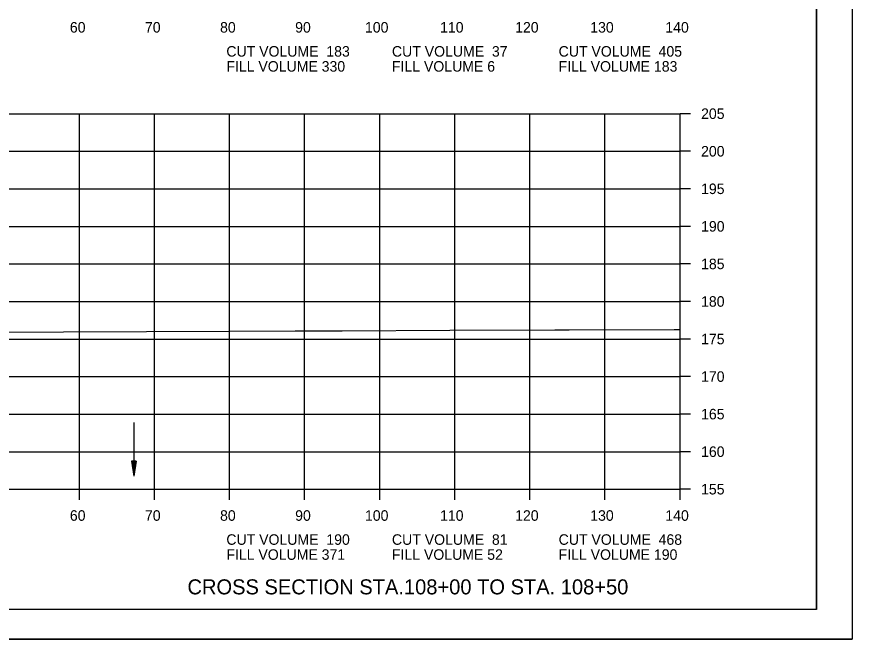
# Model space of a CAD drawing. Extents: x 1372132 to 1372465, y 380083 to 381790.
# Drawn here: x 1372353.7 to 1372464.9, y 381150.2 to 381233.1 of the extents above; entities that cross this region are included whole.
import ezdxf

# ---------------------------------------------------------------- set-up
doc = ezdxf.new("R2010")
doc.units = 0
for name, color, linetype in [('R_Axis', 7, 'Continuous'), ('R_Axis Annot', 7, 'Continuous'), ('R_Border', 7, 'Continuous'), ('R_Dimension', 7, 'Continuous'), ('R_Draft', 7, 'Continuous'), ('R_Exist Surface', 7, 'Continuous'), ('R_Grid', 7, 'Continuous'), ('R_No Plot', 7, 'Continuous')]:
    doc.layers.add(name, color=color, linetype=linetype)

msp = doc.modelspace()

# ---------------------------------------------------------------- linework, layer by layer
at = {"layer": 'R_Axis'}
for p, q in [((1372442.01, 381170.16), (1372442.01, 381220.16)), ((1372443.41, 381220.16), (1372442.01, 381220.16)), ((1372443.41, 381215.16), (1372442.01, 381215.16)), ((1372443.41, 381210.16), (1372442.01, 381210.16)), ((1372443.41, 381205.16), (1372442.01, 381205.16)), ((1372443.41, 381200.16), (1372442.01, 381200.16)), ((1372443.41, 381195.16), (1372442.01, 381195.16)), ((1372443.41, 381190.16), (1372442.01, 381190.16)), ((1372443.41, 381185.16), (1372442.01, 381185.16)), ((1372443.41, 381180.16), (1372442.01, 381180.16)), ((1372443.41, 381175.16), (1372442.01, 381175.16)), ((1372162.01, 381170.16), (1372442.01, 381170.16)), ((1372362.01, 381168.76), (1372362.01, 381170.16)), ((1372372.01, 381168.76), (1372372.01, 381170.16)), ((1372382.01, 381168.76), (1372382.01, 381170.16)), ((1372392.01, 381168.76), (1372392.01, 381170.16)), ((1372402.01, 381168.76), (1372402.01, 381170.16)), ((1372412.01, 381168.76), (1372412.01, 381170.16)), ((1372422.01, 381168.76), (1372422.01, 381170.16)), ((1372432.01, 381168.76), (1372432.01, 381170.16)), ((1372442.01, 381168.76), (1372442.01, 381170.16)), ((1372443.41, 381170.16), (1372442.01, 381170.16))]:
    msp.add_line(p, q, dxfattribs=at)
at = {"layer": 'R_Border'}
for q in [(1372460.19, 381359.62), (1372144.01, 381154.16)]:
    msp.add_line((1372460.19, 381154.16), q, dxfattribs=at)
at = {"layer": 'R_Dimension'}
for p, q in [((1372368.96, 381173.89), (1372369.26, 381171.89)), ((1372369.56, 381173.89), (1372368.96, 381173.89)), ((1372368.96, 381173.89), (1372369.26, 381171.89)), ((1372369.56, 381173.89), (1372368.96, 381173.89)), ((1372369.01, 381173.89), (1372369.26, 381172.23)), ((1372369.01, 381173.89), (1372369.26, 381172.23)), ((1372369.06, 381173.89), (1372369.26, 381172.57)), ((1372369.06, 381173.89), (1372369.26, 381172.57)), ((1372369.11, 381173.89), (1372369.26, 381172.9)), ((1372369.11, 381173.89), (1372369.26, 381172.9)), ((1372369.16, 381173.89), (1372369.26, 381173.24)), ((1372369.16, 381173.89), (1372369.26, 381173.24)), ((1372369.21, 381173.89), (1372369.26, 381173.58)), ((1372369.21, 381173.89), (1372369.26, 381173.58)), ((1372369.56, 381173.89), (1372369.26, 381171.89)), ((1372369.36, 381173.89), (1372369.26, 381173.24)), ((1372369.46, 381173.89), (1372369.26, 381172.57)), ((1372369.51, 381173.89), (1372369.26, 381172.23)), ((1372369.41, 381173.89), (1372369.26, 381172.9)), ((1372369.31, 381173.89), (1372369.26, 381173.58)), ((1372369.56, 381173.89), (1372369.26, 381171.89)), ((1372369.36, 381173.89), (1372369.26, 381173.24)), ((1372369.46, 381173.89), (1372369.26, 381172.57)), ((1372369.51, 381173.89), (1372369.26, 381172.23)), ((1372369.41, 381173.89), (1372369.26, 381172.9)), ((1372369.31, 381173.89), (1372369.26, 381173.58))]:
    msp.add_line(p, q, dxfattribs=at)
at = {"layer": 'R_Draft'}
msp.add_line((1372369.26, 381179.03), (1372369.26, 381171.89), dxfattribs=at)
at = {"layer": 'R_Exist Surface'}
msp.add_lwpolyline([(1372348.79, 381191.05), (1372382, 381191.2), (1372390.77, 381191.23), (1372395.4, 381191.25), (1372396.19, 381191.26), (1372397.03, 381191.26), (1372411.33, 381191.32), (1372425.35, 381191.38), (1372427.22, 381191.37), (1372441.23, 381191.43), (1372442.01, 381191.43)], dxfattribs=at)
at = {"layer": 'R_Grid'}
for p, q in [((1372162.01, 381220.16), (1372442.01, 381220.16)), ((1372362.01, 381170.16), (1372362.01, 381220.16)), ((1372372.01, 381170.16), (1372372.01, 381220.16)), ((1372382.01, 381170.16), (1372382.01, 381220.16)), ((1372392.01, 381170.16), (1372392.01, 381220.16)), ((1372402.01, 381170.16), (1372402.01, 381220.16)), ((1372412.01, 381170.16), (1372412.01, 381220.16)), ((1372422.01, 381170.16), (1372422.01, 381220.16)), ((1372432.01, 381170.16), (1372432.01, 381220.16)), ((1372442.01, 381170.16), (1372442.01, 381220.16)), ((1372162.01, 381215.16), (1372442.01, 381215.16)), ((1372162.01, 381210.16), (1372442.01, 381210.16)), ((1372162.01, 381205.16), (1372442.01, 381205.16)), ((1372162.01, 381200.16), (1372442.01, 381200.16)), ((1372162.01, 381195.16), (1372442.01, 381195.16)), ((1372162.01, 381190.16), (1372442.01, 381190.16)), ((1372162.01, 381185.16), (1372442.01, 381185.16)), ((1372162.01, 381180.16), (1372442.01, 381180.16)), ((1372162.01, 381175.16), (1372442.01, 381175.16)), ((1372162.01, 381170.16), (1372442.01, 381170.16))]:
    msp.add_line(p, q, dxfattribs=at)
at = {"layer": 'R_No Plot'}
msp.add_line((1372131.61, 381150.18), (1372464.95, 381150.18), dxfattribs=at)
for points in [[(1372131.61, 381363.52), (1372464.95, 381363.52), (1372464.95, 381150.18), (1372131.61, 381150.18)], [(1372377.93, 381359.62), (1372377.93, 381349.74), (1372413.67, 381349.74), (1372413.67, 381346.82), (1372436.87, 381346.82), (1372436.87, 381322.49), (1372460.19, 381322.49), (1372460.19, 381154.16), (1372144.01, 381154.16), (1372144.01, 381359.62)]]:
    msp.add_lwpolyline(points, close=True, dxfattribs=at)

# ---------------------------------------------------------------- texts
at = {"layer": 'R_Axis Annot'}
for s, p in [('60', (1372360.75, 381230.96)), ('70', (1372370.75, 381230.96)), ('80', (1372380.75, 381230.96)), ('90', (1372390.75, 381230.96)), ('100', (1372400.05, 381230.96)), ('110', (1372410.05, 381230.96)), ('120', (1372420.05, 381230.96)), ('130', (1372430.05, 381230.96)), ('140', (1372440.05, 381230.96)), ('CUT VOLUME  183', (1372381.59, 381227.76)), ('CUT VOLUME  37', (1372403.64, 381227.76)), ('CUT VOLUME  405', (1372425.84, 381227.76)), ('FILL VOLUME 330', (1372381.59, 381225.76)), ('FILL VOLUME 6', (1372403.64, 381225.76)), ('FILL VOLUME 183', (1372425.84, 381225.76)), ('205', (1372444.81, 381219.46)), ('200', (1372444.81, 381214.46)), ('195', (1372444.81, 381209.46)), ('190', (1372444.81, 381204.46)), ('185', (1372444.81, 381199.46)), ('180', (1372444.81, 381194.46)), ('175', (1372444.81, 381189.46)), ('170', (1372444.81, 381184.46)), ('165', (1372444.81, 381179.46)), ('160', (1372444.81, 381174.46)), ('155', (1372444.81, 381169.46)), ('60', (1372360.75, 381165.96)), ('70', (1372370.75, 381165.96)), ('80', (1372380.75, 381165.96)), ('90', (1372390.75, 381165.96)), ('100', (1372400.05, 381165.96)), ('110', (1372410.05, 381165.96)), ('120', (1372420.05, 381165.96)), ('130', (1372430.05, 381165.96)), ('140', (1372440.05, 381165.96)), ('CUT VOLUME  190', (1372381.59, 381162.76)), ('CUT VOLUME  81', (1372403.64, 381162.76)), ('CUT VOLUME  468', (1372425.84, 381162.76)), ('FILL VOLUME 371', (1372381.59, 381160.76)), ('FILL VOLUME 52', (1372403.64, 381160.76)), ('FILL VOLUME 190', (1372425.84, 381160.76))]:
    msp.add_text(s, height=1.4, dxfattribs=at).set_placement(p)
at = {"layer": 'R_Draft'}
msp.add_text('CROSS SECTION STA.108+00 TO STA. 108+50', height=2, dxfattribs=at).set_placement((1372376.41, 381156.16))

doc.saveas('drawing.dxf')
